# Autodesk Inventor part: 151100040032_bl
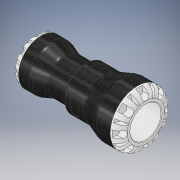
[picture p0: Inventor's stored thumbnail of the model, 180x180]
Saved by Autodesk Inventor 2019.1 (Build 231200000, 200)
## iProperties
Created: 2016-12
Part Number: 151100040032_bl
Material: PVC-Piping
Description: PLASSON G-PLASS  REDUCING COUPLING 40 x 32
Document SubType Name: Modeling
Designer: KIM
Mass: 309.689 g
Surface Area: 488.063 cm^2
Volume: 221.206 cm^3
Density: 1.4 g/cm^3
Appearance: Black Cast
Author: KIM
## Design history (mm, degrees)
derived "151100.ipt"
feature "Solid1::151100.ipt" dims "ScaleForDerivedMember" = 10
tag "TaggingFeature1"
body "Solid1"
other parameters: "d0" = 144 [user parameter], "d2" = 31.08 [user parameter], "d5" = 48 [user parameter], "d6" = 74 [user parameter], "d7" = 3.33333 [user parameter], "d8" = 58 [user parameter], "d9" = 32 [user parameter], "d11" = 23.94 [user parameter], "d12" = 57 [user parameter], "d13" = 2.66667 [user parameter], "d14" = 56 [user parameter], "d15" = 46.4 [user parameter], "d16" = 20 deg [user parameter], "d17" = 20 deg [user parameter], "d18" = 130 deg [user parameter], "d22" = 8.8 [user parameter], "d25" = 8.8 [user parameter], "d26" = 0 [user parameter], "d28" = 360 deg [user parameter], "d30" = 8 deg [user parameter], "d31" = 0.8 [user parameter], "d32" = 8 deg [user parameter], "d33" = 0.8 [user parameter], "d35" = 0 [user parameter], "d37" = 360 deg [user parameter], "d39" = 7.2 [user parameter], "d42" = 7.2 [user parameter], "d43" = 0 [user parameter], "d45" = 360 deg [user parameter], "d47" = 0.64 [user parameter], "d48" = 8 deg [user parameter], "d49" = 8 deg [user parameter], "d50" = 0.64 [user parameter], "d52" = 0 [user parameter], "d54" = 360 deg [user parameter], "d56" = 11.6 [user parameter], "d57" = 14 [user parameter], "d58" = 0.5 [user parameter], "d60" = 8.4 [user parameter], "d62" = 14.4 [user parameter], "d63" = 0 [user parameter], "d66" = 0 [user parameter], "d68" = 360 deg [user parameter], "d75" = 11.72912 [user parameter], "d77" = 54.6 [user parameter], "d78" = 0.7 [user parameter], "d1" = 32 [user parameter], "H_" = 144 [user parameter], "l_" = 74 [user parameter], "E1" = 58 [user parameter], "l1" = 57 [user parameter], "Plasson" = 1 [user parameter], "d20" = 9 [user parameter], "d21" = 11 [user parameter], "d24" = 48 [user parameter], "d40" = 58 [user parameter], "d59" = 23.45825 [user parameter]
